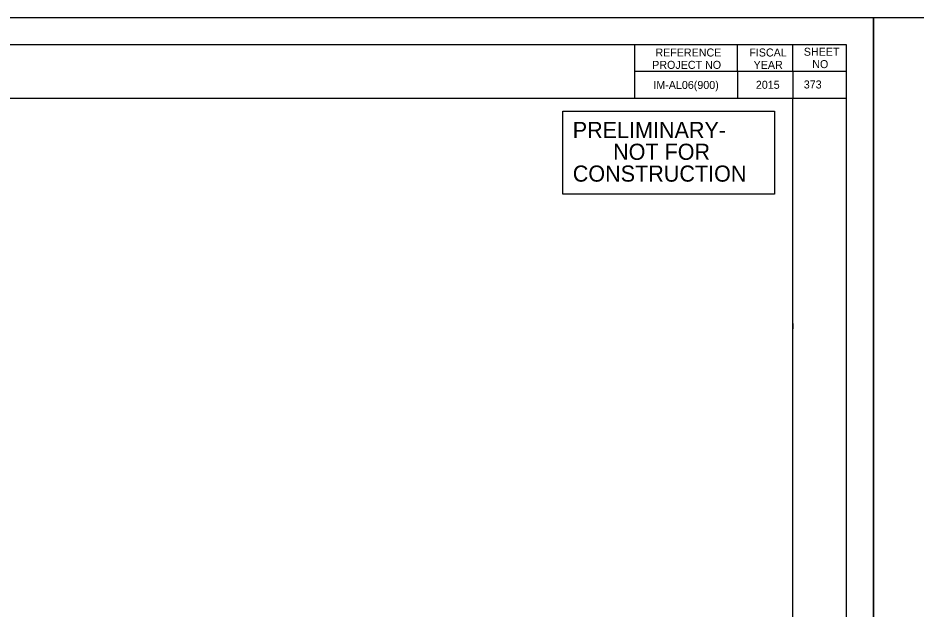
# Model space of a CAD drawing. Extents: x 1797478 to 1805176, y 246529 to 250952.
# Drawn here: x 1803656.8 to 1803823.9, y 250174.4 to 250284.4 of the extents above; entities that cross this region are included whole.
import ezdxf

# ---------------------------------------------------------------- set-up
doc = ezdxf.new("R2010")
doc.units = 0
for name, color, linetype in [('1', 7, 'Continuous'), ('2', 7, 'Continuous'), ('ANNO-SHT', 7, 'Continuous'), ('Level 6', 7, 'Continuous'), ('Level 62', 7, 'Continuous'), ('SHT-BDR', 7, 'Continuous'), ('SHT-BNDRY', 7, 'Continuous')]:
    doc.layers.add(name, color=color, linetype=linetype)

msp = doc.modelspace()

# ---------------------------------------------------------------- linework, layer by layer
at = {"layer": '1'}
msp.add_lwpolyline([(1803758.17, 250267.06), (1803797.57, 250267.06), (1803797.57, 250251.62), (1803758.17, 250251.62)], close=True, dxfattribs=at)
at = {"layer": '2'}
msp.add_lwpolyline([(1803800.97, 250227.57), (1803800.98, 250226.57)], dxfattribs=at)
msp.add_lwpolyline([(1803800.97, 250227.57), (1803800.98, 250226.57)], dxfattribs=at)
at = {"layer": 'Level 6'}
for p, q in [((1803771.55, 250279.42), (1803771.55, 250269.43)), ((1803790.71, 250274.42), (1803790.71, 250279.42)), ((1803801, 250274.55), (1803801, 250279.42)), ((1803811, 250274.48), (1803771.55, 250274.48)), ((1803790.71, 250274.42), (1803790.71, 250269.43)), ((1803801, 250274.55), (1803801, 250269.43)), ((1803811, 250269.43), (1803772.76, 250269.43))]:
    msp.add_line(p, q, dxfattribs=at)
at = {"layer": 'Level 62'}
for points in [[(1803476, 250064.42), (1803816, 250064.42), (1803816, 250284.42), (1803476, 250284.42)], [(1803816, 250064.42), (1804156, 250064.42), (1804156, 250284.42), (1803816, 250284.42)]]:
    msp.add_lwpolyline(points, close=True, dxfattribs=at)
at = {"layer": 'SHT-BDR'}
msp.add_lwpolyline([(1803501, 250079.43), (1803801, 250079.43), (1803801, 250269.43), (1803501, 250269.43)], close=True, dxfattribs=at)
at = {"layer": 'SHT-BNDRY'}
msp.add_lwpolyline([(1803488.5, 250069.42), (1803811, 250069.42), (1803811, 250279.42), (1803488.5, 250279.42)], close=True, dxfattribs=at)

# ---------------------------------------------------------------- texts
at = {"layer": '1'}
for s, p in [('PRELIMINARY-', (1803760.03, 250262.08)), ('NOT FOR', (1803767.54, 250258.02)), ('CONSTRUCTION', (1803760.04, 250253.96))]:
    msp.add_text(s, height=3, dxfattribs=at).set_placement(p)
at = {"layer": 'ANNO-SHT'}
for s, height, p in [('IM-AL06(900)', 1.4899, (1803775.03, 250271.21)), ('2015', 1.49, (1803794.11, 250271.24)), ('  373  ', 1.49, (1803801.92, 250271.3))]:
    msp.add_text(s, height=height, rotation=360, dxfattribs=at).set_placement(p)
at = {"layer": 'Level 6'}
for s, p in [('REFERENCE', (1803775.42, 250277.25)), ('FISCAL', (1803792.89, 250277.25)), ('SHEET', (1803803.04, 250277.39)), ('PROJECT NO', (1803774.82, 250274.95)), ('YEAR', (1803793.69, 250274.95)), ('NO', (1803804.61, 250275.09))]:
    msp.add_text(s, height=1.488, dxfattribs=at).set_placement(p)

doc.saveas('drawing.dxf')
